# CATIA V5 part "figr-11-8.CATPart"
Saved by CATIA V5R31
Part number: Part1
Bounding box of the stored display mesh (mm): x -50 to 50, y -39.834 to 41.856, z -25 to 25
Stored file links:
  D:\PROJECTS\Project 2021\US EDITION\CATIA V5 6R 2021\Resources\Part Files\c11_catia_v5_6r2021_prt\figr-11-8.CATPart
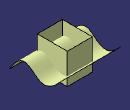
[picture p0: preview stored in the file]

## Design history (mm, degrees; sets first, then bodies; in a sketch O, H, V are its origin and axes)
Set1
  Sketch1 on yz-plane, origin (0, 0, 0), H (0, 1, 0), V (0, 0, 1)
    spline S1 through (-39.8338, -18.0686) (-4.7892, 0) (1.9431, -5.3632) (41.8556, 3.6938)
    point P1 (-4.7892, 0)
    coincidence: P1 H
  Extrude1: Element1 Sketch1, Lim1 50, Lim2 50, Direction yz-plane
  Sketch2 on xy-plane, origin (0, 0, 0), H (1, 0, 0), V (0, 1, 0)
    line L1 (-20.1634, 25.5896) -> (20.7534, 25.5896)
    line L2 (20.7534, 25.5896) -> (20.7534, -23.3463)
    line L3 (20.7534, -23.3463) -> (-20.1634, -23.3463)
    line L4 (-20.1634, -23.3463) -> (-20.1634, 25.5896)
    horizontal: L1 H, L3 H
    vertical: L2 V, L4 V
  Extrude2: Element1 Sketch2, Lim1 25, Lim2 25, Direction xy-plane
Body1 (main body)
